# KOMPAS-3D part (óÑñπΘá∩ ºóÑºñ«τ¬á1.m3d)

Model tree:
1. Эскиз:1
2. Операция выдавливания:1
     Расстояние 1 = 9.3
3. Эскиз:2
4. Операция выдавливания:2
     Расстояние 1 = 4; Угол 1 = 62.7
5. Эскиз:3
6. Операция выдавливания:3
     Расстояние 1 = 2.5
7. Эскиз:4
8. Операция выдавливания:4
     Расстояние 1 = 2.6
9. Эскиз:5
10. Операция выдавливания:5
     Расстояние 1 = 2.6
11. Эскиз:6
12. Вырезать элемент выдавливания:1
     Расстояние 1 = 21
13. Массив по концентрической сетке:1  (with: Вырезать элемент выдавливания:1)  (labels: Экземпляр ( 1, 1 ); Экземпляр ( 1, 2 ); Экземпляр ( 1, 3 ); Экземпляр ( 1, 4 ))
     N 2 = 14; Шаг 2 = 360; Номер 2 = 1
14. Эскиз:7
15. Вырезать элемент выдавливания:2
     Расстояние 1 = 0.5
16. Эскиз:8
17. Вырезать элемент выдавливания:3
     Расстояние 1 = 0.5
18. Массив по концентрической сетке:2  (with: Вырезать элемент выдавливания:3)  (labels: Экземпляр ( 1, 1 ); Экземпляр ( 1, 2 ); Экземпляр ( 1, 3 ); Экземпляр ( 1, 4 ))
     N 2 = 14; Шаг 2 = 360; Номер 2 = 1
19. Эскиз:36
20. Вырезать элемент выдавливания:15
     Расстояние 1 = 0.5
21. Эскиз:39
22. Вырезать элемент выдавливания:18
     Расстояние 1 = 1
23. Скругление:18
     Радиус = 0.5
24. Скругление:19
     Радиус = 0.2
25. Скругление:20
     Радиус = 0.5
26. Эскиз:40
27. Вырезать элемент выдавливания:19
     Расстояние 1 = 0.5
28. Эскиз:41
29. Вырезать элемент выдавливания:20
     Расстояние 1 = 0.5
30. Массив по концентрической сетке:11  (with: Вырезать элемент выдавливания:20)  (labels: Экземпляр ( 1, 1 ); Экземпляр ( 1, 2 ); Экземпляр ( 1, 3 ); Экземпляр ( 1, 4 ))
     N 2 = 14; Шаг 2 = 360; Номер 2 = 1
31. Эскиз:42
32. Вырезать элемент выдавливания:21
     Расстояние 1 = 0.5
33. Эскиз:43
34. Вырезать элемент выдавливания:22
     Расстояние 1 = 1
35. Скругление:21
     Радиус = 0.2
36. Эскиз:47
37. Отверстие:4
38. Эскиз:48
39. Операция выдавливания:20
     Расстояние 1 = 0.7; Расстояние 2 = 15
40. Эскиз:68
41. Вырезать элемент выдавливания:28
     Расстояние 1 = 5
42. Эскиз:69
43. Операция выдавливания:30
     Расстояние 1 = 0.7; Расстояние 2 = 11
44. Эскиз:70
45. Вырезать элемент выдавливания:29
     Расстояние 1 = 0.5
46. Массив по концентрической сетке:17  (with: Операция выдавливания:30, Вырезать элемент выдавливания:29)  (labels: Экземпляр ( 1, 1 ); Экземпляр ( 1, 2 ); Экземпляр ( 1, 3 ); Экземпляр ( 1, 4 ))
     N 2 = 14; Шаг 2 = 360; Номер 2 = 1
47. Смещенная плоскость:3
     Расстояние = 10.3
48. Эскиз:73
49. Операция выдавливания:32
     Расстояние 1 = 10; Расстояние 2 = 10.5
50. Эскиз:75
51. Вырезать элемент выдавливания:32
     Расстояние 1 = 2.7
52. Эскиз:76
53. Вырезать элемент выдавливания:33
     Расстояние 1 = 3
54. Эскиз:77
55. Вырезать элемент выдавливания:34
     Расстояние 1 = 18.3
56. Скругление:28
     Радиус = 1
57. Скругление:29
     Радиус = 0.5
58. Скругление:30
     Радиус = 0.5
59. Скругление:32
     Радиус = 0.5

Referenced files in C:\Program Files\ASCON\KOMPAS-3D V13 Home\Sys\: holelib.lfr
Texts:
  stalker61
  Сплав АЛ8  ГОСТ 1583-93
  Отверстие 02
  (вариант 2)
